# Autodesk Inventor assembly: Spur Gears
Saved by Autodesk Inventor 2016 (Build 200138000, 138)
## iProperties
Created: 2015-08
Part Number: Spur Gears
Document SubType Name: Assembly
Designer: Ugljesa
Categories: <?xml version="1.0" encoding="UTF-16"?> <MemberInstance><Categories><FamilyTemplate/><ParamToTemplateMap><ParamToTemplate><ParamToTemplate CategoryParameter="//
Mass: 203.429 g
Surface Area: 109.446 cm^2
Volume: 25.9145 cm^3
Density: 7.85 g/cm^3
ClientObjectVersion: 1
Author: Ugljesa
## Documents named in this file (2)
- E:\Turbokompr\Sklop turbokompresora\Design Accelerator\Spur Gears3.iam
- E:\Turbokompr\Sklop turbokompresora\Design Accelerator\Spur Gear23.ipt
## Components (1 placed, 1 different names)
1. Spur Gear2:1
